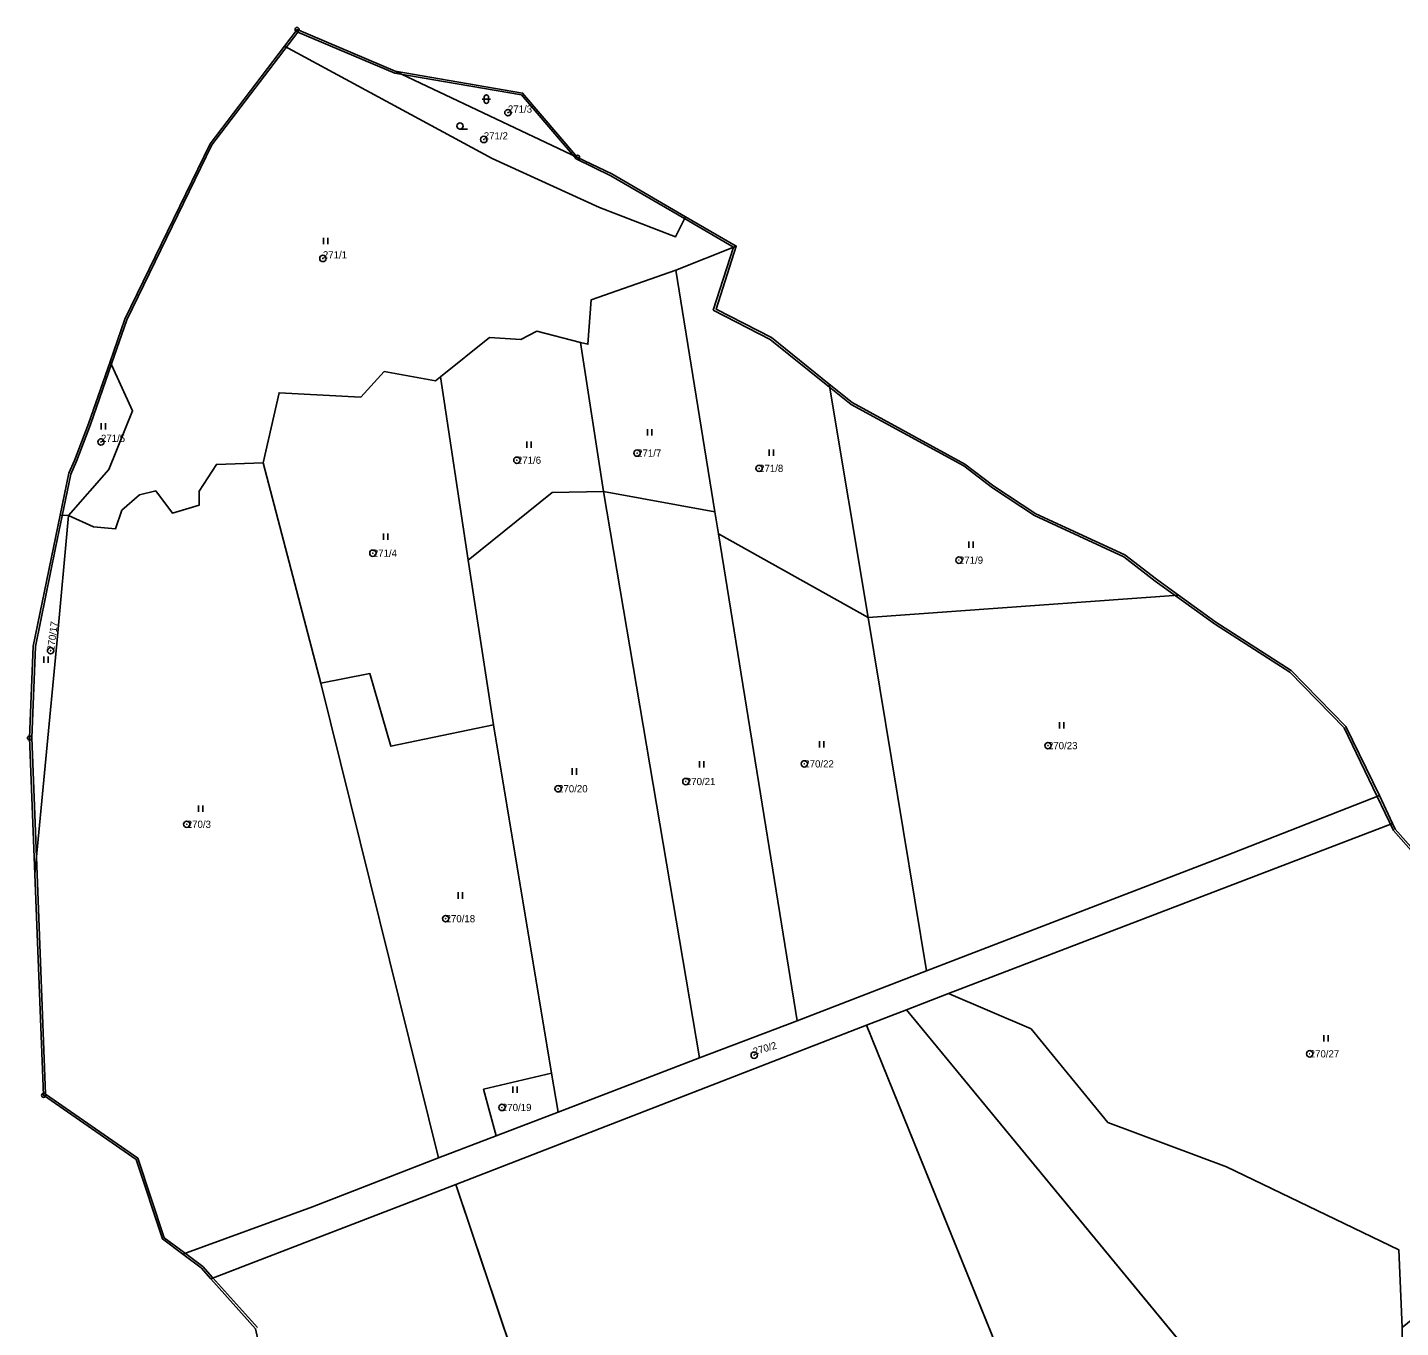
# Model space of a CAD drawing. Extents: x -652854 to -650068, y -1097661 to -1095417.
# Drawn here: x -652264.6 to -651941.1, y -1096194.7 to -1095888.5 of the extents above; entities that cross this region are included whole.
import ezdxf

# ---------------------------------------------------------------- set-up
doc = ezdxf.new("R2010")
doc.units = 0
for name, color, linetype in [('Definiční body parcel', 7, 'Continuous'), ('Geodetické body', 7, 'Continuous'), ('Hranice obcí', 7, 'Continuous'), ('Hranice parcel', 7, 'Continuous'), ('Obvody jako plochy', 7, 'Continuous'), ('Ostatní hranice', 7, 'Continuous'), ('Parcelní čísla', 7, 'Continuous'), ('Značky kultur', 7, 'Continuous')]:
    doc.layers.add(name, color=color, linetype=linetype)

msp = doc.modelspace()

# ---------------------------------------------------------------- linework, layer by layer
at = {"layer": 'Definiční body parcel'}
for centre, radius in [((-652151.44, -1095908.6), 0.75), ((-652151.44, -1095908.6), 0.0327), ((-652157.13, -1095914.91), 0.75), ((-652157.13, -1095914.91), 0.0327), ((-652195.03, -1095942.93), 0.75), ((-652195.03, -1095942.93), 0.0327), ((-652247.32, -1095986.15), 0.75), ((-652247.32, -1095986.15), 0.0327), ((-652121, -1095988.78), 0.75), ((-652121, -1095988.78), 0.0327), ((-652149.32, -1095990.46), 0.75), ((-652149.32, -1095990.46), 0.0327), ((-652092.26, -1095992.38), 0.75), ((-652092.26, -1095992.38), 0.0327), ((-652183.26, -1096012.36), 0.75), ((-652183.26, -1096012.36), 0.0327), ((-652045.18, -1096014), 0.75), ((-652045.18, -1096014), 0.0327), ((-652259.19, -1096035.33), 0.75), ((-652259.19, -1096035.33), 0.0327), ((-652024.21, -1096057.68), 0.75), ((-652024.21, -1096057.68), 0.0327), ((-652081.61, -1096061.98), 0.75), ((-652081.61, -1096061.98), 0.0327), ((-652109.51, -1096066.14), 0.75), ((-652109.51, -1096066.14), 0.0327), ((-652139.62, -1096067.84), 0.75), ((-652139.62, -1096067.84), 0.0327), ((-652227.1, -1096076.21), 0.75), ((-652227.1, -1096076.21), 0.0327), ((-652166.12, -1096098.44), 0.75), ((-652166.12, -1096098.44), 0.0327), ((-652093.42, -1096130.6), 0.75), ((-652093.42, -1096130.6), 0.0327), ((-651962.54, -1096130.28), 0.75), ((-651962.54, -1096130.28), 0.0327), ((-652152.85, -1096142.91), 0.75), ((-652152.85, -1096142.91), 0.0327)]:
    msp.add_circle(centre, radius, dxfattribs=at)
at = {"layer": 'Geodetické body'}
for centre, radius in [((-652201.1, -1095889.03), 0.5), ((-652201.1, -1095889.03), 0.001), ((-652135.04, -1095919.12), 0.5), ((-652135.04, -1095919.12), 0.001), ((-652264.14, -1096055.88), 0.5), ((-652264.14, -1096055.88), 0.001), ((-652260.83, -1096140.04), 0.5), ((-652260.83, -1096140.04), 0.001)]:
    msp.add_circle(centre, radius, dxfattribs=at)
at = {"layer": 'Hranice obcí'}
for p, q in [((-652204.08, -1095892.93), (-652201.1, -1095889.03)), ((-652201.1, -1095889.03), (-652177.97, -1095898.83)), ((-652221.61, -1095915.91), (-652204.08, -1095892.93)), ((-652177.97, -1095898.83), (-652148, -1095904)), ((-652148, -1095904), (-652135.04, -1095919.12)), ((-652241.7, -1095957.25), (-652221.61, -1095915.91)), ((-652135.04, -1095919.12), (-652126.99, -1095923.03)), ((-652126.99, -1095923.03), (-652109.57, -1095933.12)), ((-652109.57, -1095933.12), (-652097.66, -1095940.02)), ((-652097.66, -1095940.02), (-652102.39, -1095954.87)), ((-652102.39, -1095954.87), (-652089.38, -1095961.56)), ((-652245.19, -1095967.31), (-652241.7, -1095957.25)), ((-652089.38, -1095961.56), (-652075.73, -1095972.54)), ((-652250.28, -1095981.88), (-652245.19, -1095967.31)), ((-652075.73, -1095972.54), (-652070.32, -1095976.89)), ((-652070.32, -1095976.89), (-652043.79, -1095991.35)), ((-652253.57, -1095990.5), (-652250.28, -1095981.88)), ((-652254.9, -1095993.54), (-652253.57, -1095990.5)), ((-652043.79, -1095991.35), (-652036.93, -1095996.54)), ((-652256.93, -1096003.4), (-652254.9, -1095993.54)), ((-652036.93, -1095996.54), (-652027.09, -1096003.1)), ((-652258.5, -1096011.01), (-652256.93, -1096003.4)), ((-652027.09, -1096003.1), (-652006.11, -1096012.77)), ((-652263.27, -1096034.26), (-652258.5, -1096011.01)), ((-652006.11, -1096012.77), (-651998.63, -1096018.51)), ((-651998.63, -1096018.51), (-651993.46, -1096022.25)), ((-651993.46, -1096022.25), (-651984.66, -1096028.62)), ((-651984.66, -1096028.62), (-651966.91, -1096040)), ((-652264.14, -1096055.88), (-652263.27, -1096034.26)), ((-651966.91, -1096040), (-651954, -1096053.18)), ((-651954, -1096053.18), (-651946.13, -1096069.45)), ((-652264.14, -1096055.88), (-652262.88, -1096087.95)), ((-651946.13, -1096069.45), (-651943.06, -1096076)), ((-651943.06, -1096076), (-651942.4, -1096077.39)), ((-651942.4, -1096077.39), (-651917.43, -1096105.58)), ((-652262.88, -1096087.95), (-652260.83, -1096140.04)), ((-652238.99, -1096155.16), (-652260.83, -1096140.04)), ((-652232.82, -1096173.89), (-652238.99, -1096155.16)), ((-652228.06, -1096177.45), (-652232.82, -1096173.89)), ((-652223.74, -1096180.68), (-652228.06, -1096177.45)), ((-652221.45, -1096183.25), (-652223.74, -1096180.68)), ((-652210.9, -1096195.04), (-652221.45, -1096183.25))]:
    msp.add_line(p, q, dxfattribs=at)
at = {"layer": 'Hranice parcel'}
for p, q in [((-652155.12, -1095919.41), (-652204.08, -1095892.93)), ((-652135.04, -1095919.12), (-652177.97, -1095898.83)), ((-652129.85, -1095930.91), (-652155.12, -1095919.41)), ((-652111.98, -1095937.87), (-652129.85, -1095930.91)), ((-652109.57, -1095933.12), (-652111.98, -1095937.87)), ((-652097.66, -1095940.02), (-652111.85, -1095945.7)), ((-652111.85, -1095945.7), (-652131.8, -1095952.67)), ((-652102.67, -1096002.6), (-652111.85, -1095945.7)), ((-652131.8, -1095952.67), (-652132.58, -1095963.15)), ((-652155.81, -1095961.59), (-652167.3, -1095970.78)), ((-652148.38, -1095962.06), (-652155.81, -1095961.59)), ((-652144.63, -1095960.1), (-652148.38, -1095962.06)), ((-652134.35, -1095962.7), (-652144.63, -1095960.1)), ((-652128.89, -1095997.84), (-652134.35, -1095962.7)), ((-652132.58, -1095963.15), (-652134.35, -1095962.7)), ((-652245.19, -1095967.31), (-652239.86, -1095978.83)), ((-652180.57, -1095969.57), (-652186.12, -1095975.59)), ((-652168.52, -1095971.76), (-652180.57, -1095969.57)), ((-652167.3, -1095970.78), (-652168.52, -1095971.76)), ((-652160.82, -1096013.99), (-652167.3, -1095970.78)), ((-652066.56, -1096027.47), (-652075.73, -1095972.54)), ((-652205.34, -1095974.57), (-652209.13, -1095991.04)), ((-652186.12, -1095975.59), (-652205.34, -1095974.57)), ((-652239.86, -1095978.83), (-652245.49, -1095992.66)), ((-652220.12, -1095991.45), (-652224.19, -1095997.78)), ((-652209.13, -1095991.04), (-652220.12, -1095991.45)), ((-652195.5, -1096042.95), (-652209.13, -1095991.04)), ((-652245.49, -1095992.66), (-652254.94, -1096003.47)), ((-652234.41, -1095997.7), (-652238.25, -1095998.63)), ((-652230.45, -1096002.94), (-652234.41, -1095997.7)), ((-652224.19, -1095997.78), (-652224.19, -1096001.06)), ((-652160.82, -1096013.99), (-652140.98, -1095998.07)), ((-652140.98, -1095998.07), (-652128.89, -1095997.84)), ((-652106.31, -1096131.21), (-652128.89, -1095997.84)), ((-652128.89, -1095997.84), (-652102.67, -1096002.6)), ((-652238.25, -1095998.63), (-652242.39, -1096002.23)), ((-652224.19, -1096001.06), (-652230.45, -1096002.94)), ((-652254.94, -1096003.47), (-652257.73, -1096033.61)), ((-652254.94, -1096003.47), (-652256.93, -1096003.4)), ((-652249.08, -1096006.13), (-652254.94, -1096003.47)), ((-652242.39, -1096002.23), (-652243.88, -1096006.61)), ((-652101.82, -1096007.8), (-652102.67, -1096002.6)), ((-652243.88, -1096006.61), (-652249.08, -1096006.13)), ((-652083.31, -1096122.52), (-652101.82, -1096007.8)), ((-652101.82, -1096007.8), (-652066.56, -1096027.47)), ((-652154.81, -1096052.81), (-652160.82, -1096013.99)), ((-652066.56, -1096027.47), (-651993.46, -1096022.25)), ((-652052.82, -1096110.7), (-652066.56, -1096027.47)), ((-652257.73, -1096033.61), (-652262.88, -1096087.95)), ((-652195.5, -1096042.95), (-652184.01, -1096040.73)), ((-652167.77, -1096154.81), (-652195.5, -1096042.95)), ((-652184.01, -1096040.73), (-652179, -1096057.83)), ((-652179, -1096057.83), (-652154.81, -1096052.81)), ((-652141.17, -1096134.81), (-652154.81, -1096052.81)), ((-651946.13, -1096069.45), (-651982.36, -1096083.67)), ((-651943.06, -1096076), (-652047.62, -1096116.05)), ((-651982.36, -1096083.67), (-652052.82, -1096110.7)), ((-652052.82, -1096110.7), (-652083.31, -1096122.52)), ((-652047.62, -1096116.05), (-652057.53, -1096119.89)), ((-652047.62, -1096116.05), (-652028.17, -1096124.39)), ((-652057.53, -1096119.89), (-652066.96, -1096123.51)), ((-652057.53, -1096119.89), (-651988.88, -1096203.13)), ((-652066.96, -1096123.51), (-652163.72, -1096161.03)), ((-652083.31, -1096122.52), (-652106.31, -1096131.21)), ((-652066.96, -1096123.51), (-652022.53, -1096233.18)), ((-652028.17, -1096124.39), (-652010.08, -1096146.47)), ((-652106.31, -1096131.21), (-652139.58, -1096144.02)), ((-652141.17, -1096134.81), (-652157.18, -1096138.64)), ((-652139.58, -1096144.02), (-652141.17, -1096134.81)), ((-652157.18, -1096138.64), (-652154.23, -1096149.63)), ((-652139.58, -1096144.02), (-652154.23, -1096149.63)), ((-652010.08, -1096146.47), (-651982.15, -1096156.91)), ((-652154.23, -1096149.63), (-652167.77, -1096154.81)), ((-652167.77, -1096154.81), (-652197.49, -1096166.29)), ((-651982.15, -1096156.91), (-651941.55, -1096176.41)), ((-652163.72, -1096161.03), (-652221.45, -1096183.25)), ((-652163.72, -1096161.03), (-652140.38, -1096230.48)), ((-652197.49, -1096166.29), (-652228.06, -1096177.45)), ((-651941.55, -1096176.41), (-651940.73, -1096194.74))]:
    msp.add_line(p, q, dxfattribs=at)
at = {"layer": 'Obvody jako plochy'}
for points in [[(-652129.85, -1095930.91), (-652111.98, -1095937.87), (-652109.57, -1095933.12), (-652126.99, -1095923.03), (-652135.04, -1095919.12), (-652177.97, -1095898.83), (-652201.1, -1095889.03), (-652204.08, -1095892.93), (-652155.12, -1095919.41)], [(-652129.85, -1095930.91), (-652155.12, -1095919.41), (-652204.08, -1095892.93), (-652221.61, -1095915.91), (-652241.7, -1095957.25), (-652245.19, -1095967.31), (-652239.86, -1095978.83), (-652245.49, -1095992.66), (-652254.94, -1096003.47), (-652249.08, -1096006.13), (-652243.88, -1096006.61), (-652242.39, -1096002.23), (-652238.25, -1095998.63), (-652234.41, -1095997.7), (-652230.45, -1096002.94), (-652224.19, -1096001.06), (-652224.19, -1095997.78), (-652220.12, -1095991.45), (-652209.13, -1095991.04), (-652205.34, -1095974.57), (-652186.12, -1095975.59), (-652180.57, -1095969.57), (-652168.52, -1095971.76), (-652167.3, -1095970.78), (-652155.81, -1095961.59), (-652148.38, -1095962.06), (-652144.63, -1095960.1), (-652134.35, -1095962.7), (-652132.58, -1095963.15), (-652131.8, -1095952.67), (-652111.85, -1095945.7), (-652097.66, -1095940.02), (-652109.57, -1095933.12), (-652111.98, -1095937.87)], [(-652177.97, -1095898.83), (-652135.04, -1095919.12), (-652148, -1095904)], [(-652101.82, -1096007.8), (-652066.56, -1096027.47), (-652075.73, -1095972.54), (-652089.38, -1095961.56), (-652102.39, -1095954.87), (-652097.66, -1095940.02), (-652111.85, -1095945.7), (-652102.67, -1096002.6)], [(-652111.85, -1095945.7), (-652131.8, -1095952.67), (-652132.58, -1095963.15), (-652134.35, -1095962.7), (-652128.89, -1095997.84), (-652102.67, -1096002.6)], [(-652144.63, -1095960.1), (-652148.38, -1095962.06), (-652155.81, -1095961.59), (-652167.3, -1095970.78), (-652160.82, -1096013.99), (-652140.98, -1095998.07), (-652128.89, -1095997.84), (-652134.35, -1095962.7)], [(-652239.86, -1095978.83), (-652245.19, -1095967.31), (-652250.28, -1095981.88), (-652253.57, -1095990.5), (-652254.9, -1095993.54), (-652256.93, -1096003.4), (-652254.94, -1096003.47), (-652245.49, -1095992.66)], [(-652168.52, -1095971.76), (-652180.57, -1095969.57), (-652186.12, -1095975.59), (-652205.34, -1095974.57), (-652209.13, -1095991.04), (-652195.5, -1096042.95), (-652184.01, -1096040.73), (-652179, -1096057.83), (-652154.81, -1096052.81), (-652160.82, -1096013.99), (-652167.3, -1095970.78)], [(-651998.63, -1096018.51), (-652006.11, -1096012.77), (-652027.09, -1096003.1), (-652036.93, -1095996.54), (-652043.79, -1095991.35), (-652070.32, -1095976.89), (-652075.73, -1095972.54), (-652066.56, -1096027.47), (-651993.46, -1096022.25)], [(-652220.12, -1095991.45), (-652224.19, -1095997.78), (-652224.19, -1096001.06), (-652230.45, -1096002.94), (-652234.41, -1095997.7), (-652238.25, -1095998.63), (-652242.39, -1096002.23), (-652243.88, -1096006.61), (-652249.08, -1096006.13), (-652254.94, -1096003.47), (-652257.73, -1096033.61), (-652262.88, -1096087.95), (-652260.83, -1096140.04), (-652238.99, -1096155.16), (-652232.82, -1096173.89), (-652228.06, -1096177.45), (-652197.49, -1096166.29), (-652167.77, -1096154.81), (-652195.5, -1096042.95), (-652209.13, -1095991.04)], [(-652106.31, -1096131.21), (-652128.89, -1095997.84), (-652140.98, -1095998.07), (-652160.82, -1096013.99), (-652154.81, -1096052.81), (-652141.17, -1096134.81), (-652139.58, -1096144.02)], [(-652083.31, -1096122.52), (-652101.82, -1096007.8), (-652102.67, -1096002.6), (-652128.89, -1095997.84), (-652106.31, -1096131.21)], [(-652254.94, -1096003.47), (-652256.93, -1096003.4), (-652258.5, -1096011.01), (-652263.27, -1096034.26), (-652264.14, -1096055.88), (-652262.88, -1096087.95), (-652257.73, -1096033.61)], [(-652101.82, -1096007.8), (-652083.31, -1096122.52), (-652052.82, -1096110.7), (-652066.56, -1096027.47)], [(-652066.56, -1096027.47), (-652052.82, -1096110.7), (-651982.36, -1096083.67), (-651946.13, -1096069.45), (-651954, -1096053.18), (-651966.91, -1096040), (-651984.66, -1096028.62), (-651993.46, -1096022.25)], [(-652184.01, -1096040.73), (-652195.5, -1096042.95), (-652167.77, -1096154.81), (-652154.23, -1096149.63), (-652157.18, -1096138.64), (-652141.17, -1096134.81), (-652154.81, -1096052.81), (-652179, -1096057.83)], [(-652223.74, -1096180.68), (-652221.45, -1096183.25), (-652163.72, -1096161.03), (-652066.96, -1096123.51), (-652057.53, -1096119.89), (-652047.62, -1096116.05), (-651943.06, -1096076), (-651946.13, -1096069.45), (-651982.36, -1096083.67), (-652052.82, -1096110.7), (-652083.31, -1096122.52), (-652106.31, -1096131.21), (-652139.58, -1096144.02), (-652154.23, -1096149.63), (-652167.77, -1096154.81), (-652197.49, -1096166.29), (-652228.06, -1096177.45)], [(-651943.06, -1096076), (-652047.62, -1096116.05), (-652028.17, -1096124.39), (-652010.08, -1096146.47), (-651982.15, -1096156.91), (-651941.55, -1096176.41), (-651940.73, -1096194.74), (-651858.99, -1096128.33), (-651909.94, -1096111.5), (-651917.43, -1096105.58), (-651942.4, -1096077.39)], [(-652047.62, -1096116.05), (-652057.53, -1096119.89), (-651988.88, -1096203.13), (-651935.29, -1096301.66), (-651889.71, -1096389.26), (-651881.07, -1096385.89), (-651862.37, -1096368.4), (-651859.22, -1096330.24), (-651863.16, -1096325.62), (-651893.8, -1096290.17), (-651915.5, -1096264.18), (-651935.12, -1096240.7), (-651940.57, -1096214.69), (-651940.73, -1096194.74), (-651941.55, -1096176.41), (-651982.15, -1096156.91), (-652010.08, -1096146.47), (-652028.17, -1096124.39)], [(-652057.53, -1096119.89), (-652066.96, -1096123.51), (-652022.53, -1096233.18), (-652036.99, -1096246.19), (-651992.07, -1096427.63), (-651981.51, -1096423.32), (-651963.26, -1096417), (-651946.95, -1096410.49), (-651915.68, -1096399.4), (-651889.71, -1096389.26), (-651935.29, -1096301.66), (-651988.88, -1096203.13)], [(-652066.96, -1096123.51), (-652163.72, -1096161.03), (-652140.38, -1096230.48), (-652113.66, -1096314.2), (-652109.04, -1096349.86), (-652116.16, -1096395.34), (-652122.68, -1096396.82), (-652121.39, -1096400.54), (-652095.82, -1096426.92), (-652039.13, -1096456.38), (-652018.96, -1096438.6), (-651992.07, -1096427.63), (-652036.99, -1096246.19), (-652022.53, -1096233.18)], [(-652139.58, -1096144.02), (-652141.17, -1096134.81), (-652157.18, -1096138.64), (-652154.23, -1096149.63)], [(-652163.72, -1096161.03), (-652221.45, -1096183.25), (-652210.9, -1096195.04), (-652199.14, -1096246.92), (-652140.38, -1096230.48)]]:
    msp.add_lwpolyline(points, close=True, dxfattribs=at)
at = {"layer": 'Ostatní hranice'}
for p, q in [((-652221.2, -1095916.21), (-652200.94, -1095889.63)), ((-652178.08, -1095899.33), (-652200.94, -1095889.63)), ((-652178.08, -1095899.33), (-652148.28, -1095904.43)), ((-652148.28, -1095904.43), (-652135.37, -1095919.51)), ((-652241.22, -1095957.42), (-652221.2, -1095916.21)), ((-652135.37, -1095919.51), (-652127.23, -1095923.48)), ((-652127.23, -1095923.48), (-652109.83, -1095933.56)), ((-652109.83, -1095933.56), (-652098.27, -1095940.25)), ((-652098.27, -1095940.25), (-652103.05, -1095955.13)), ((-652103.05, -1095955.13), (-652089.66, -1095961.99)), ((-652244.74, -1095967.53), (-652241.22, -1095957.42)), ((-652089.66, -1095961.99), (-652076.04, -1095972.94)), ((-652249.81, -1095982.07), (-652244.74, -1095967.53)), ((-652076.04, -1095972.94), (-652070.6, -1095977.32)), ((-652070.6, -1095977.32), (-652044.03, -1095991.8)), ((-652253.09, -1095990.65), (-652249.81, -1095982.07)), ((-652254.43, -1095993.72), (-652253.09, -1095990.65)), ((-652044.03, -1095991.8), (-652037.24, -1095996.94)), ((-652256.44, -1096003.53), (-652254.43, -1095993.72)), ((-652037.24, -1095996.94), (-652027.4, -1096003.51)), ((-652258.01, -1096011.11), (-652256.44, -1096003.53)), ((-652027.4, -1096003.51), (-652006.34, -1096013.23)), ((-652262.78, -1096034.37), (-652258.01, -1096011.11)), ((-652006.34, -1096013.23), (-651998.93, -1096018.92)), ((-651998.93, -1096018.92), (-651993.72, -1096022.69)), ((-651993.72, -1096022.69), (-651984.97, -1096029.03)), ((-651984.97, -1096029.03), (-651967.23, -1096040.4)), ((-652263.63, -1096055.88), (-652262.78, -1096034.37)), ((-651967.23, -1096040.4), (-651954.41, -1096053.48)), ((-651954.41, -1096053.48), (-651942.82, -1096077.69)), ((-652262.37, -1096087.99), (-652263.63, -1096055.88)), ((-651942.82, -1096077.69), (-651917.8, -1096105.94)), ((-652262.37, -1096087.99), (-652260.38, -1096139.74)), ((-652238.6, -1096154.85), (-652260.38, -1096139.74)), ((-652232.42, -1096173.58), (-652238.6, -1096154.85)), ((-652227.73, -1096177.06), (-652232.42, -1096173.58)), ((-652223.35, -1096180.35), (-652227.73, -1096177.06)), ((-652221.05, -1096182.93), (-652223.35, -1096180.35)), ((-652210.48, -1096194.75), (-652221.05, -1096182.93))]:
    msp.add_line(p, q, dxfattribs=at)
at = {"layer": 'Značky kultur'}
for p, q in [((-652157.51, -1095905.42), (-652155.51, -1095905.42)), ((-652157.01, -1095905.92), (-652157.01, -1095904.92)), ((-652156.01, -1095905.92), (-652156.01, -1095904.92)), ((-652160.99, -1095912.5), (-652162.74, -1095912.5)), ((-652194.927, -1095938.075), (-652194.927, -1095939.575)), ((-652193.905, -1095939.575), (-652193.905, -1095938.075)), ((-652247.287, -1095981.705), (-652247.287, -1095983.205)), ((-652246.265, -1095983.205), (-652246.265, -1095981.705)), ((-652118.557, -1095983.175), (-652118.557, -1095984.675)), ((-652117.535, -1095984.675), (-652117.535, -1095983.175)), ((-652146.987, -1095986.025), (-652146.987, -1095987.525)), ((-652145.965, -1095987.525), (-652145.965, -1095986.025)), ((-652089.897, -1095987.945), (-652089.897, -1095989.445)), ((-652088.875, -1095989.445), (-652088.875, -1095987.945)), ((-652180.747, -1096007.745), (-652180.747, -1096009.245)), ((-652179.725, -1096009.245), (-652179.725, -1096007.745)), ((-652042.847, -1096009.565), (-652042.847, -1096011.065)), ((-652041.825, -1096011.065), (-652041.825, -1096009.565)), ((-652260.747, -1096036.715), (-652260.747, -1096038.215)), ((-652259.725, -1096038.215), (-652259.725, -1096036.715)), ((-652021.507, -1096052.185), (-652021.507, -1096053.685)), ((-652020.485, -1096053.685), (-652020.485, -1096052.185)), ((-652078.037, -1096056.655), (-652078.037, -1096058.155)), ((-652077.015, -1096058.155), (-652077.015, -1096056.655)), ((-652136.307, -1096063.025), (-652136.307, -1096064.525)), ((-652135.285, -1096064.525), (-652135.285, -1096063.025)), ((-652106.297, -1096061.345), (-652106.297, -1096062.845)), ((-652105.275, -1096062.845), (-652105.275, -1096061.345)), ((-652224.357, -1096071.775), (-652224.357, -1096073.275)), ((-652223.335, -1096073.275), (-652223.335, -1096071.775)), ((-652163.127, -1096092.235), (-652163.127, -1096093.735)), ((-652162.105, -1096093.735), (-652162.105, -1096092.235)), ((-651959.237, -1096125.845), (-651959.237, -1096127.345)), ((-651958.215, -1096127.345), (-651958.215, -1096125.845)), ((-652150.287, -1096137.985), (-652150.287, -1096139.485)), ((-652149.265, -1096139.485), (-652149.265, -1096137.985))]:
    msp.add_line(p, q, dxfattribs=at)
msp.add_circle((-652162.74, -1095911.75), 0.75, dxfattribs=at)
for centre, start, end in [((-652156.51, -1095904.92), 0, 180), ((-652156.51, -1095905.92), 180, 0)]:
    msp.add_arc(centre, 0.5, start, end, dxfattribs=at)

# ---------------------------------------------------------------- texts
at = {"layer": 'Parcelní čísla'}
for s, p in [('271/3', (-652151.44, -1095908.6)), ('271/2', (-652157.13, -1095914.91)), ('271/1', (-652195.03, -1095942.93)), ('271/5', (-652247.32, -1095986.15)), ('271/7', (-652121, -1095989.63)), ('271/6', (-652149.32, -1095991.31)), ('271/8', (-652092.26, -1095993.23)), ('271/4', (-652183.26, -1096013.21)), ('271/9', (-652045.18, -1096014.85)), ('270/23', (-652024.21, -1096058.53)), ('270/22', (-652081.61, -1096062.83)), ('270/21', (-652109.51, -1096066.99)), ('270/20', (-652139.62, -1096068.69)), ('270/3', (-652227.1, -1096077.06)), ('270/18', (-652166.12, -1096099.29)), ('270/27', (-651962.54, -1096131.13)), ('270/19', (-652152.85, -1096143.76))]:
    msp.add_text(s, height=1.7, dxfattribs=at).set_placement(p)
for s, rotation, p in [('270/17', 82.503, (-652258.347, -1096035.441)), ('270/2', 16.137, (-652093.42, -1096130.6))]:
    msp.add_text(s, height=1.7, rotation=rotation, dxfattribs=at).set_placement(p)

doc.saveas('drawing.dxf')
